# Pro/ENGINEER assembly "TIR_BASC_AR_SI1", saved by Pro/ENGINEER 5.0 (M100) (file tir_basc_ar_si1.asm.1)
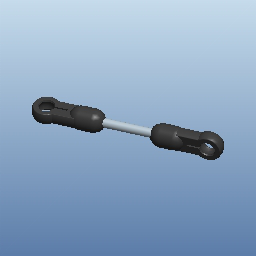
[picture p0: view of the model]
Units: millimeter Newton Second (mmNs); MM, TONNE, HOURS

Other components: 80022001-CHAPE_STD_DR_SI1, 80022001-CHAPE_STD_DR_SI1, TIR_ACIER_LG0_62

Other named items: 80022001-CHAPE_STD_DR_01, 80465046-TIR_ACIER_LG_46_01, A-DROITE, A-DESSUS, A-FACE, A-R0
